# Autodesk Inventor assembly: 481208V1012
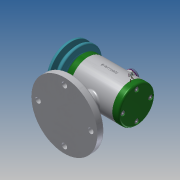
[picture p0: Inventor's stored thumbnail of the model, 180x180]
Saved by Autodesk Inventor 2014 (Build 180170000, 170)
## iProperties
Created: 2018-12
Part Number: 481208V1012
Document SubType Name: Assembly
Designer: 601-24
Author: 601-24
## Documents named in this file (16)
- C:\Users\601-24\Desktop\481208V1012\답안조립품.iam
- C:\Users\601-24\Desktop\481208V1012\481208V1012.ipt
- C:\Users\601-24\Desktop\481208V1012\V벨트풀리.ipt
- C:\Users\601-24\Desktop\481208V1012\고무캡.ipt
- C:\Users\601-24\Desktop\481208V1012\너트 M8.ipt
- 너트 M8.ipt
- C:\Users\601-24\Desktop\481208V1012\뒤커버.ipt
- C:\Users\601-24\Desktop\481208V1012\베어링 15 x 32 x 9.ipt
- C:\Users\601-24\Desktop\481208V1012\볼트 M4 x 12.ipt
- C:\Users\601-24\Desktop\481208V1012\스프링와셔 8.ipt
- C:\Users\601-24\Desktop\481208V1012\앞커버.ipt
- C:\Users\601-24\Desktop\481208V1012\오일 실 15 25 7.ipt
- C:\Users\601-24\Desktop\481208V1012\와셔 8x17.ipt
- C:\Users\601-24\Desktop\481208V1012\축.ipt
- C:\Users\601-24\Desktop\481208V1012\키 3 x 3 x 12.ipt
- C:\Users\601-24\Desktop\481208V1012\본체.ipt
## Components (3 placed, 3 different names)
1. 481208V1012:1
2. V벨트풀리:1 — 각도:2
3. 고무캡:1 — 각도:4
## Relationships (2: Angle 2)
- 각도:2 [Angle]: V벨트풀리:1
- 각도:4 [Angle]: 고무캡:1
